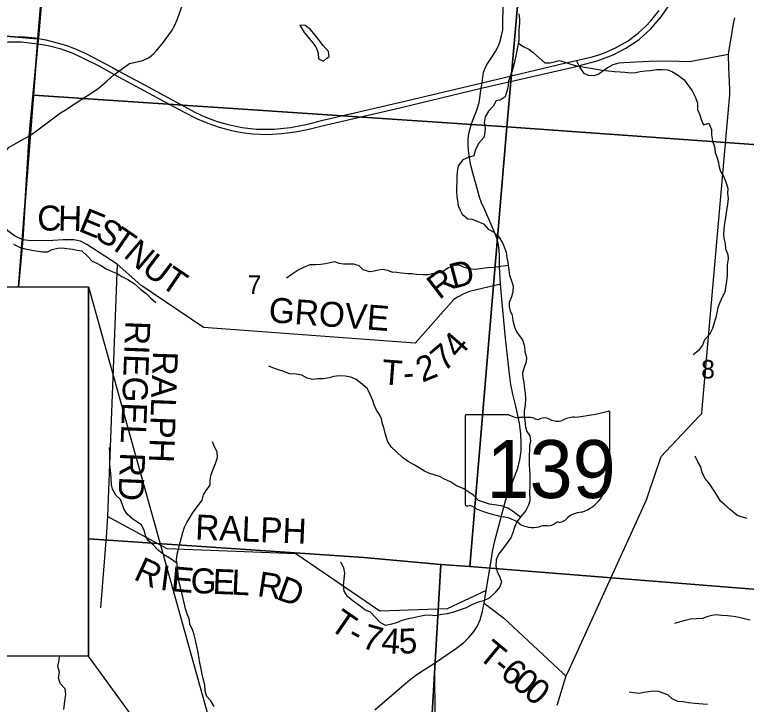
# Model space of a CAD drawing. Extents: x 0 to 34, y 0 to 22.
# Drawn here: x 26.174 to 27.839, y 17.514 to 19.082 of the extents above; entities that cross this region are included whole.
import ezdxf

# ---------------------------------------------------------------- set-up
doc = ezdxf.new("R2010")
doc.units = 0
for name, color, linetype in [('GM_X_Corporation', 7, 'Continuous'), ('GM_X_County_Road', 7, 'Continuous'), ('GM_X_Minor_Lake', 7, 'Continuous'), ('GM_X_Minor_River', 7, 'Continuous'), ('GM_X_Section_Text', 7, 'Continuous'), ('GM_X_State_Location', 7, 'Continuous'), ('GM_X_State_Route', 7, 'Continuous'), ('GM_X_State_Shield', 7, 'Continuous'), ('GM_X_Township_Road', 7, 'Continuous'), ('GM_X_Township_Road_Text', 7, 'Continuous'), ('SH_Data', 7, 'Continuous')]:
    doc.layers.add(name, color=color, linetype=linetype)

msp = doc.modelspace()

# ---------------------------------------------------------------- linework, layer by layer
at = {"layer": 'GM_X_Corporation'}
for points in [[(26.1825, 18.4635), (26.1926, 18.5708), (26.207, 18.8068), (26.2271, 19.0168), (26.2277, 19.0233), (26.2281, 19.0286), (26.3029, 19.931), (25.7174, 19.9778), (25.482, 19.99), (25.2916, 20.0037), (25.117, 20.0172), (24.3889, 20.0736), (24.2296, 20.084), (23.8215, 20.1257), (23.5167, 20.1476), (23.5167, 14.1), (25.8273, 14.1), (25.8671, 14.5774), (25.9626, 15.7291)], [(26.3029, 19.931), (26.2281, 19.0286), (26.2277, 19.0233), (26.2271, 19.0168), (26.207, 18.8068), (26.1926, 18.5708), (26.1825, 18.4635)], [(25.1756, 18.4635), (25.2286, 19.1118), (26.2267, 19.0272), (26.2169, 18.8995), (26.1832, 18.4635)], [(26.1832, 18.4635), (26.2169, 18.8995), (27.2938, 18.8276), (27.2101, 17.8272), (27.1442, 17.8319), (26.9688, 17.8482), (26.3421, 17.8905)], [(26.3421, 17.8905), (26.9688, 17.8482), (27.1442, 17.8319), (27.1132, 17.3107), (27.1145, 16.8163), (26.06, 16.9257), (26.0658, 16.9791), (26.1183, 17.6235)]]:
    msp.add_lwpolyline(points, dxfattribs=at)
for points in [[(26.302, 19.9328), (26.2267, 19.0272), (25.2286, 19.1118), (25.2979, 20.0049)], [(27.3834, 19.8411), (27.2938, 18.8276), (26.2169, 18.8995), (26.2267, 19.0272), (26.302, 19.9328)], [(27.4311, 19.8373), (28.3876, 19.7694), (28.2889, 18.7562), (27.2938, 18.8276), (27.3834, 19.8411)], [(27.2938, 18.8276), (28.2889, 18.7562), (28.2146, 17.7472), (27.2101, 17.8272)], [(27.1442, 17.8319), (27.2101, 17.8272), (28.2146, 17.7472), (28.2741, 17.7417), (28.199, 16.7653), (27.1145, 16.8163), (27.1132, 17.3107)]]:
    msp.add_lwpolyline(points, close=True, dxfattribs=at)
at = {"layer": 'GM_X_County_Road'}
for points in [[(26.4975, 19.0018), (26.5104, 19.017), (26.5312, 19.0447), (26.5381, 19.0566), (26.5437, 19.0706), (26.5623, 19.1231)], [(26.2872, 18.8644), (26.3142, 18.882), (26.3636, 18.9139), (26.3846, 18.9317), (26.4009, 18.9463), (26.403, 18.9479), (26.4085, 18.9518), (26.4115, 18.954), (26.4249, 18.964), (26.4352, 18.9715), (26.4659, 18.9784), (26.4803, 18.9847), (26.491, 18.9942), (26.4975, 19.0018)], [(26.1967, 18.8005), (26.2072, 18.8063), (26.2241, 18.818), (26.2788, 18.8589), (26.2872, 18.8644)], [(25.5296, 18.4635), (25.6325, 18.5008), (25.6385, 18.503), (25.6487, 18.5126), (25.7159, 18.5755), (25.7363, 18.5751), (25.9101, 18.5708), (25.9139, 18.5707), (25.9301, 18.5741), (26.0384, 18.5952), (26.0505, 18.6033), (26.0725, 18.6261), (26.1085, 18.6647), (26.1162, 18.6788), (26.1224, 18.6983), (26.1347, 18.7397), (26.1421, 18.755), (26.1524, 18.7703), (26.1618, 18.7812), (26.1967, 18.8005)]]:
    msp.add_lwpolyline(points, dxfattribs=at)
at = {"layer": 'GM_X_Minor_Lake'}
for points in [[(26.8231, 19.0581), (26.8325, 19.0418), (26.8529, 19.0182), (26.8601, 19.008), (26.8646, 18.9951), (26.8657, 18.9822), (26.8767, 18.9769), (26.8842, 18.9831)], [(26.8842, 18.9831), (26.8896, 18.9875), (26.8881, 18.9989), (26.876, 19.0118), (26.8662, 19.0247), (26.8571, 19.0368), (26.8469, 19.0482), (26.8352, 19.0577), (26.8231, 19.0581)]]:
    msp.add_lwpolyline(points, dxfattribs=at)
at = {"layer": 'GM_X_Minor_River'}
for points in [[(27.3211, 19.0842), (27.3232, 19.0721), (27.3228, 19.0626), (27.3216, 19.0489), (27.3214, 19.0232), (27.3194, 19.0122), (27.3171, 19), (27.3147, 18.9883), (27.312, 18.9781), (27.31, 18.9679), (27.3065, 18.9542), (27.3023, 18.9444), (27.2981, 18.9308), (27.2969, 18.9213), (27.2945, 18.9103), (27.2899, 18.8956), (27.2792, 18.8877), (27.2698, 18.8862), (27.2632, 18.8745), (27.2526, 18.8628), (27.2445, 18.8496), (27.2426, 18.8367), (27.2447, 18.8242), (27.2443, 18.8143), (27.2419, 18.8026), (27.2301, 18.7898), (27.2228, 18.7758), (27.2186, 18.7614), (27.2057, 18.7573), (27.1939, 18.7521), (27.1829, 18.7389), (27.1809, 18.7252), (27.1804, 18.7139), (27.1803, 18.701), (27.1795, 18.6911), (27.1794, 18.6797), (27.1805, 18.6691), (27.1816, 18.6592), (27.1834, 18.6475), (27.1875, 18.638), (27.1923, 18.6284), (27.2055, 18.6177)], [(27.3204, 19.0175), (27.3315, 19.0102), (27.344, 19.0037), (27.3541, 18.996), (27.3677, 18.9838), (27.3805, 18.9731), (27.3918, 18.9726), (27.4024, 18.9748), (27.413, 18.9782), (27.424, 18.9754), (27.4372, 18.9704), (27.4497, 18.9665), (27.4625, 18.9642), (27.475, 18.9618), (27.4852, 18.9606), (27.4984, 18.9586), (27.5109, 18.9559), (27.5253, 18.9543), (27.5389, 18.9531), (27.5517, 18.9522), (27.5627, 18.9514), (27.5767, 18.9501), (27.5865, 18.9505), (27.5972, 18.953), (27.6104, 18.9545), (27.621, 18.9555), (27.6346, 18.9577), (27.6475, 18.9576), (27.66, 18.9568), (27.6706, 18.9525), (27.6845, 18.9441), (27.6977, 18.9338), (27.7074, 18.9208), (27.716, 18.9094), (27.7231, 18.8938), (27.7276, 18.8812), (27.7282, 18.8664), (27.7331, 18.8547), (27.736, 18.844), (27.7413, 18.8318), (27.7534, 18.8356), (27.7597, 18.8215), (27.76, 18.809), (27.7618, 18.7957), (27.7663, 18.7828), (27.7677, 18.7687), (27.7722, 18.7588), (27.7751, 18.7482), (27.7769, 18.7364), (27.7803, 18.7258), (27.7881, 18.7136), (27.7941, 18.698), (27.7966, 18.687), (27.7962, 18.6756), (27.7973, 18.6646), (27.7964, 18.6513), (27.794, 18.6373), (27.7925, 18.6275), (27.7905, 18.6161), (27.7889, 18.6032), (27.7881, 18.593), (27.7869, 18.5835), (27.7879, 18.574), (27.7905, 18.5619), (27.7919, 18.5497), (27.7968, 18.5372), (27.7978, 18.5269), (27.7951, 18.5133), (27.7954, 18.5038), (27.7957, 18.4898), (27.7937, 18.4761), (27.7913, 18.4617), (27.7897, 18.4515), (27.7844, 18.4413), (27.779, 18.4281), (27.7744, 18.4163), (27.7716, 18.4042), (27.7693, 18.394), (27.765, 18.3792), (27.7616, 18.3683), (27.7554, 18.3554), (27.7436, 18.3426), (27.739, 18.3305), (27.7291, 18.318), (27.718, 18.3086)], [(27.2055, 18.6177), (27.2153, 18.6173), (27.2278, 18.6119), (27.2406, 18.6065), (27.2519, 18.5947), (27.2647, 18.5878), (27.276, 18.5771), (27.2842, 18.5637), (27.2879, 18.5542), (27.2924, 18.5424), (27.2942, 18.5295), (27.296, 18.5193), (27.2978, 18.5068), (27.3004, 18.49), (27.3048, 18.4771), (27.3085, 18.465), (27.3077, 18.4517), (27.3046, 18.4407), (27.2992, 18.4279), (27.2991, 18.418), (27.3013, 18.4085), (27.3058, 18.399), (27.3076, 18.3865), (27.3113, 18.3724), (27.3154, 18.3625), (27.3218, 18.353), (27.3293, 18.3431), (27.3345, 18.3286), (27.3351, 18.3165), (27.3384, 18.3024), (27.338, 18.293), (27.3337, 18.2797), (27.3299, 18.2672), (27.3302, 18.257), (27.3328, 18.2456), (27.3345, 18.2308), (27.336, 18.2213), (27.3367, 18.2095), (27.3358, 18.1944), (27.3338, 18.1811), (27.3338, 18.1709), (27.3348, 18.1591), (27.3362, 18.1443), (27.3396, 18.1348), (27.3463, 18.1245), (27.3481, 18.1127), (27.3454, 18.1029), (27.3453, 18.0911), (27.3449, 18.0817), (27.3448, 18.0722), (27.3451, 18.0585), (27.3454, 18.0483), (27.3465, 18.0358), (27.3463, 18.0096), (27.3458, 17.9986), (27.3461, 17.9771)], [(26.1713, 18.5605), (26.1864, 18.5532), (26.1981, 18.5501), (26.2132, 18.5466), (26.2378, 18.5427), (26.2491, 18.543), (26.2594, 18.5486), (26.2727, 18.5515), (26.2833, 18.5518), (26.2931, 18.5506), (26.3063, 18.549), (26.3165, 18.5471), (26.3271, 18.5451), (26.3403, 18.5321), (26.3508, 18.5218), (26.361, 18.5176), (26.3715, 18.511), (26.3825, 18.5045), (26.396, 18.498), (26.407, 18.4934), (26.4179, 18.4872), (26.4315, 18.4799), (26.4462, 18.4707), (26.4612, 18.4577), (26.4736, 18.4482), (26.483, 18.4386), (26.4955, 18.4275)], [(27.2971, 18.5117), (27.2751, 18.5092), (27.2642, 18.5077), (27.2501, 18.5067), (27.2342, 18.5045), (27.2225, 18.5031), (27.2081, 18.5047), (27.1976, 18.507), (27.1859, 18.5124), (27.1734, 18.5121), (27.1601, 18.5058), (27.1475, 18.4979), (27.1354, 18.4946), (27.1248, 18.4931), (27.1153, 18.4909), (27.1036, 18.491), (27.0885, 18.4911), (27.0783, 18.4931), (27.0684, 18.4927), (27.0537, 18.4944), (27.0438, 18.4959), (27.0333, 18.4964), (27.0223, 18.5006), (27.0117, 18.5026), (27.0019, 18.5011), (26.992, 18.4993), (26.9822, 18.4979), (26.9674, 18.5018), (26.9577, 18.5109), (26.9456, 18.5148), (26.9335, 18.5149), (26.9225, 18.5153), (26.9127, 18.5165), (26.9029, 18.52), (26.8911, 18.5182), (26.8813, 18.5156), (26.871, 18.5145), (26.8585, 18.5135), (26.8457, 18.5132), (26.8316, 18.5076), (26.8195, 18.5016), (26.8058, 18.4922), (26.7929, 18.4832)], [(27.2299, 17.9773), (27.2182, 17.9896), (27.2058, 17.9976), (27.196, 18.0038), (27.1794, 18.0111), (27.1662, 18.0199), (27.1523, 18.0264), (27.141, 18.0318), (27.1308, 18.0349), (27.1168, 18.04), (27.1066, 18.0446), (27.0946, 18.0519), (27.0817, 18.0591), (27.0693, 18.0664), (27.0565, 18.0756), (27.0437, 18.0875), (27.0313, 18.0989), (27.0231, 18.1107), (27.0201, 18.121), (27.0171, 18.1309), (27.0149, 18.1404), (27.0112, 18.1522), (27.009, 18.1636), (27.0042, 18.1731), (26.9974, 18.1826), (26.9918, 18.1951), (26.9893, 18.205), (26.9833, 18.2187), (26.977, 18.2313), (26.9649, 18.2424), (26.951, 18.2527), (26.9389, 18.2577), (26.9265, 18.2604), (26.9128, 18.2609), (26.9007, 18.2595), (26.8901, 18.2565), (26.8772, 18.2543), (26.8636, 18.254), (26.8515, 18.253), (26.8394, 18.2561), (26.8273, 18.2622), (26.8145, 18.2646), (26.7993, 18.2658), (26.7869, 18.2712), (26.7771, 18.274), (26.765, 18.2778), (26.7522, 18.2828)], [(26.4147, 17.9797), (26.4042, 17.9896), (26.397, 18.0036), (26.3948, 18.0143), (26.3934, 18.0283), (26.3926, 18.0389), (26.3904, 18.0594), (26.3909, 18.0727), (26.3909, 18.0859), (26.3898, 18.0984)], [(26.6007, 17.9787), (26.6041, 17.9903), (26.6102, 18.0001), (26.6186, 18.0126), (26.6187, 18.022), (26.6207, 18.0345), (26.6261, 18.0485), (26.6311, 18.0618), (26.6353, 18.0754), (26.6347, 18.0883), (26.6283, 18.1009), (26.6242, 18.1108)], [(27.7801, 17.9762), (27.7711, 17.9912), (27.764, 18.0015), (27.7557, 18.0144), (27.7449, 18.0285), (27.7385, 18.0411), (27.7352, 18.054), (27.7285, 18.0658), (27.7225, 18.078)], [(26.5432, 17.8354), (26.5258, 17.847), (26.513, 17.8546), (26.5009, 17.8649), (26.4904, 17.8763), (26.4783, 17.8858), (26.4723, 17.8957), (26.469, 17.9097), (26.4626, 17.9219), (26.452, 17.9288), (26.4422, 17.9356), (26.4309, 17.9455), (26.4234, 17.9569), (26.4147, 17.9797)], [(26.6065, 17.5586), (26.6028, 17.5722), (26.6005, 17.5825), (26.5987, 17.5942), (26.5957, 17.6083), (26.5931, 17.6231), (26.5909, 17.636), (26.5875, 17.6496), (26.5853, 17.6602), (26.5827, 17.6724), (26.579, 17.6845), (26.573, 17.6955), (26.5719, 17.7062), (26.5677, 17.7179), (26.5632, 17.7312), (26.5595, 17.7452), (26.5569, 17.7574), (26.5543, 17.7676), (26.5521, 17.7771), (26.5495, 17.7881), (26.5472, 17.7991), (26.5461, 17.8094), (26.5454, 17.8188), (26.5436, 17.8321), (26.5425, 17.8427), (26.544, 17.8556), (26.5471, 17.867), (26.5506, 17.8817), (26.554, 17.8931), (26.5571, 17.9045), (26.5609, 17.9173), (26.5659, 17.9276), (26.5723, 17.9374), (26.5784, 17.9491), (26.6007, 17.9787)], [(27.3461, 17.9771), (27.3434, 17.9667), (27.3369, 17.9549), (27.3267, 17.9421), (27.3164, 17.9289), (27.3111, 17.9167), (27.3084, 17.9065), (27.3034, 17.8929), (27.2951, 17.8816), (27.2867, 17.8698), (27.2753, 17.8555), (27.27, 17.8426), (27.2691, 17.8293), (27.2721, 17.8157), (27.2774, 17.8058), (27.2815, 17.7929), (27.278, 17.7812), (27.2666, 17.7676), (27.2537, 17.7555), (27.2409, 17.7498), (27.2284, 17.7461), (27.214, 17.7405), (27.2018, 17.7337), (27.1821, 17.7269), (27.1723, 17.7239), (27.1579, 17.7198), (27.1458, 17.7184), (27.1314, 17.7154), (27.1174, 17.717), (27.1064, 17.7159), (27.0951, 17.7136), (27.0814, 17.711), (27.0693, 17.7088), (27.0553, 17.7047), (27.0432, 17.6994), (27.0315, 17.6964), (27.0186, 17.6931), (27.0061, 17.6999), (26.9952, 17.7114), (26.9839, 17.7235), (26.9711, 17.7293), (26.9575, 17.7396), (26.9443, 17.7487), (26.9318, 17.7594), (26.9239, 17.7712), (26.9221, 17.784), (26.9236, 17.7988), (26.9256, 17.8125), (26.923, 17.8246), (26.9162, 17.8371)], [(27.3248, 17.9397), (27.3093, 17.952), (27.2961, 17.9604), (27.281, 17.9658), (27.2544, 17.9694), (27.2299, 17.9773)], [(27.8408, 17.9363), (27.8272, 17.9402), (27.817, 17.944), (27.8026, 17.9566), (27.7902, 17.9676), (27.7801, 17.9762)], [(27.8475, 17.7054), (27.835, 17.7085), (27.8229, 17.7112), (27.8097, 17.7135), (27.7961, 17.7151), (27.7828, 17.7163), (27.77, 17.7175), (27.7598, 17.7164), (27.7492, 17.7134), (27.7389, 17.7093), (27.7249, 17.7082), (27.7117, 17.7075), (27.6996, 17.7049), (27.6886, 17.7015), (27.6753, 17.6978)], [(26.2862, 17.5025), (26.2874, 17.5147), (26.2894, 17.5272), (26.2905, 17.5366), (26.2894, 17.5495), (26.2774, 17.5617), (26.274, 17.5742), (26.2763, 17.5875), (26.2722, 17.6004), (26.2757, 17.6148), (26.276, 17.6235)], [(26.6279, 17.5092), (26.6207, 17.5217), (26.6117, 17.5316), (26.6076, 17.5442), (26.6065, 17.5586)], [(27.7503, 17.514), (27.7401, 17.5144), (27.722, 17.5156), (27.7076, 17.5172), (27.6951, 17.5199), (27.683, 17.5203), (27.6705, 17.5264), (27.6604, 17.536), (27.6494, 17.5398), (27.6392, 17.5429), (27.626, 17.5437), (27.6161, 17.5422), (27.6055, 17.5411), (27.5957, 17.5389), (27.5821, 17.5404), (27.5722, 17.542)]]:
    msp.add_lwpolyline(points, dxfattribs=at)
at = {"layer": 'GM_X_State_Route'}
msp.add_line((27.2359, 18.9148), (27.4588, 18.9662), dxfattribs=at)
for points in [[(27.4588, 18.9662), (27.4595, 18.9664), (27.4998, 18.9775), (27.5357, 18.991), (27.5651, 19.0059), (27.595, 19.0259), (27.6217, 19.05), (27.6448, 19.0777), (27.6634, 19.1041), (27.6789, 19.1351), (27.6893, 19.1642), (27.696, 19.1907), (27.6996, 19.2171), (27.7018, 19.2443), (27.7026, 19.2826), (27.7041, 19.3538), (27.7065, 19.4779), (27.7095, 19.6149), (27.7111, 19.7195), (27.7114, 19.7325)], [(26.9933, 17.5012), (27.0652, 17.5627), (27.0839, 17.5779), (27.0987, 17.5882), (27.1295, 17.6076), (27.1794, 17.6421), (27.1952, 17.6541), (27.2079, 17.666), (27.2173, 17.6774), (27.2265, 17.6908), (27.2334, 17.7064), (27.2385, 17.7263), (27.2421, 17.7439), (27.2467, 17.7732), (27.258, 17.8401), (27.2615, 17.8613), (27.2667, 17.8856), (27.2916, 17.9802), (27.319, 18.0513), (27.3238, 18.0702), (27.3266, 18.0896), (27.3267, 18.1094), (27.3261, 18.1283), (27.3231, 18.1534), (27.3143, 18.1922), (27.3077, 18.2194), (27.3034, 18.2411), (27.2991, 18.2716), (27.2912, 18.3468), (27.2837, 18.4272), (27.2796, 18.4694), (27.2774, 18.5088), (27.2774, 18.533), (27.2764, 18.5478), (27.275, 18.5591), (27.2717, 18.5716), (27.2672, 18.5843), (27.2437, 18.6382), (27.2363, 18.6546), (27.232, 18.6674), (27.2123, 18.7395), (27.2092, 18.7564), (27.2066, 18.7735), (27.2059, 18.7861), (27.2062, 18.7988), (27.2077, 18.8118), (27.2132, 18.8318), (27.2192, 18.8481), (27.226, 18.8655), (27.2312, 18.8828), (27.2359, 18.9148), (27.2376, 18.9276), (27.2406, 18.9517), (27.2478, 18.9673), (27.257, 18.9808), (27.2679, 18.9986), (27.274, 19.0102), (27.2779, 19.0199), (27.2812, 19.0308), (27.2846, 19.0478), (27.2873, 19.2517)], [(26.4115, 18.954), (26.4609, 18.9276), (26.5854, 18.8602), (26.6109, 18.8487), (26.6347, 18.8395), (26.66, 18.8323), (26.6915, 18.8254), (26.724, 18.8222), (26.7648, 18.8222), (26.8015, 18.8257), (26.8412, 18.8334), (26.8752, 18.8421), (27.0523, 18.8834), (27.2376, 18.9276), (27.4286, 18.9724), (27.4524, 18.9779), (27.4718, 18.9825), (27.4881, 18.9867), (27.5059, 18.9918), (27.5217, 18.9979), (27.5431, 19.0075), (27.5703, 19.023), (27.5938, 19.0406), (27.6106, 19.0558), (27.6212, 19.0673), (27.6408, 19.0914)], [(26.168, 19.033), (26.1973, 19.0318), (26.221, 19.0293), (26.2283, 19.0281), (26.2447, 19.0252), (26.2676, 19.0193), (26.2906, 19.0126), (26.3144, 19.0037), (26.3375, 18.9936), (26.3969, 18.9618), (26.4115, 18.954)], [(25.3496, 18.6702), (25.4138, 18.7006), (25.5277, 18.7538), (25.7087, 18.8396), (25.8629, 18.913), (25.981, 18.9686), (26.0152, 18.985), (26.0417, 18.9962), (26.0701, 19.0054), (26.1024, 19.014), (26.1315, 19.0186), (26.1601, 19.0207), (26.1899, 19.0202), (26.2273, 19.0163), (26.2503, 19.012), (26.2766, 19.0051), (26.3063, 18.9944), (26.3317, 18.9829), (26.3654, 18.9656), (26.4009, 18.9463)], [(26.4009, 18.9463), (26.5259, 18.8785), (26.5595, 18.8605), (26.5897, 18.8452), (26.6136, 18.8353), (26.6391, 18.8265), (26.6673, 18.8187), (26.6911, 18.8143), (26.7158, 18.8113), (26.7502, 18.8098), (26.7821, 18.8117), (26.8127, 18.8158), (26.8406, 18.8214), (26.8735, 18.8293), (27.0507, 18.8705), (27.2359, 18.9148)]]:
    msp.add_lwpolyline(points, dxfattribs=at)
at = {"layer": 'GM_X_State_Shield'}
for p, q in [((27.1991, 18.1691), (27.1991, 17.969)), ((27.2989, 18.1726), (27.2023, 18.1726)), ((27.5287, 18.0729), (27.5287, 18.1775)), ((27.5286, 18.0729), (27.5287, 18.0729))]:
    msp.add_line(p, q, dxfattribs=at)
for centre, major_axis, start_param, end_param in [((27.2029, 18.1696), (0.00382, 0), 1.712693, 3.28349), ((27.3218, 18.1958), (0.037, 0), 4.042523, 4.731795), ((27.3341, 18.0602), (0.133, 0), 1.404758, 1.657858), ((27.3643, 18.1706), (0.0107, 0), 3.836095, 5.185415), ((27.38, 18.1475), (0.0222, 0), 0.950623, 2.079405), ((27.4559, 18.1115), (0.0703, 0), 1.699011, 2.107814), ((27.4113, 18.4454), (0.3495, 0), 4.814394, 5.042369), ((27.525, 18.178), (0.00367, 0), 6.141152, 7.989035), ((27.4087, 18.1792), (0.0267, 0), 4.081561, 5.145723), ((27.5278, 18.0652), (0.00568, 0), 1.883978, 3.671073), ((27.5248, 18.0725), (0.00393, 0), 5.05454, 6.418171), ((27.4917, 18.0519), (0.0341, 0), 5.934695, 6.695948), ((27.5418, 18.0291), (0.0248, 0), 2.387724, 3.262537), ((27.4309, 18.0157), (0.0874, 0), 5.101752, 6.440018), ((27.2029, 17.9686), (0.00385, 0), 3.00124, 4.508301), ((27.2035, 17.9891), (0.0294, 0), 4.665946, 4.897461), ((27.2095, 17.9575), (0.0106, 0), 0.519207, 1.627899), ((27.3433, 18.1373), (0.2524, 0), 4.195997, 4.488961), ((27.4677, 17.9128), (0.0479, 0), 1.647645, 2.488434), ((27.2681, 17.8791), (0.079, 0), 0.823519, 1.323587), ((27.4071, 17.9496), (0.0282, 0), 4.937069, 5.64225), ((27.3535, 17.9565), (0.0501, 0), 4.026481, 4.996735), ((27.3824, 17.8873), (0.0412, 0), 1.495662, 1.94098), ((27.3861, 17.9415), (0.0267, 0), 4.691044, 5.507374), ((27.4103, 17.9221), (0.00752, 0), 1.147584, 2.315152)]:
    msp.add_ellipse(centre, major_axis=major_axis, ratio=0.8, start_param=start_param, end_param=end_param, dxfattribs=at)
at = {"layer": 'GM_X_Township_Road'}
msp.add_line((26.3814, 17.8855), (26.3697, 17.7338), dxfattribs=at)
for points in [[(27.7985, 18.9915), (27.8002, 19.002), (27.8108, 19.0649), (27.8125, 19.0754)], [(27.4082, 17.5124), (27.4262, 17.5693), (27.4292, 17.5788), (27.4334, 17.5879), (27.6115, 17.9788), (27.618, 17.9976), (27.6439, 18.0732), (27.6454, 18.0776), (27.6559, 18.0887), (27.7312, 18.1687), (27.7377, 18.1756), (27.7386, 18.1861), (27.801, 18.8925), (27.8015, 18.8996), (27.8011, 18.9124), (27.7994, 18.9623), (27.7985, 18.9915), (27.71, 18.9749), (27.6618, 18.9766), (27.6177, 18.9758), (27.5745, 18.9737), (27.5603, 18.9727)], [(27.5603, 18.9727), (27.5491, 18.9719), (27.5351, 18.9683), (27.5233, 18.9613), (27.5031, 18.947), (27.4917, 18.9429), (27.48, 18.9441), (27.4703, 18.9487), (27.4636, 18.9574), (27.4588, 18.9662), (27.4524, 18.9779)], [(26.2609, 18.5685), (26.2519, 18.568), (26.2052, 18.5687), (26.1928, 18.5702), (26.174, 18.5797), (26.1588, 18.5907), (26.136, 18.6227), (26.1085, 18.6647)], [(27.2796, 18.4694), (27.2087, 18.4525), (27.1946, 18.4471), (27.1816, 18.4398), (27.1737, 18.4344), (27.0856, 18.3351), (26.6036, 18.3711), (26.4611, 18.4673), (26.4072, 18.5147), (26.3387, 18.5599), (26.3241, 18.567), (26.3088, 18.57), (26.2847, 18.57), (26.2609, 18.5685)], [(26.4072, 18.5147), (26.3856, 17.9412), (26.382, 17.8942), (26.3814, 17.8855)], [(27.2467, 17.7732), (27.1579, 17.7309), (27.0052, 17.7259), (26.8136, 17.8566), (26.521, 17.868), (26.3856, 17.9412)], [(27.2421, 17.7439), (27.2868, 17.7109), (27.4217, 17.5851), (27.4292, 17.5788)], [(27.1295, 17.6076), (27.1302, 17.4692), (27.1094, 17.3183), (27.1089, 17.0285), (27.1135, 16.8092), (27.107, 16.5939), (27.1034, 16.3274)]]:
    msp.add_lwpolyline(points, dxfattribs=at)
at = {"layer": 'SH_Data'}
for points in [[(24.656, 18.4635), (26.3421, 18.4635), (26.3421, 17.6235), (24.656, 17.6235)], [(26.3421, 18.4635), (26.7223, 17.1016), (26.3421, 17.6235)]]:
    msp.add_lwpolyline(points, close=True, dxfattribs=at)

# ---------------------------------------------------------------- texts
at = {"layer": 'GM_X_Section_Text'}
for s, p in [('7', (26.7042, 18.4473)), ('8', (27.7362, 18.2551))]:
    msp.add_text(s, height=0.0419, rotation=0, dxfattribs=at).set_placement(p)
at = {"layer": 'GM_X_State_Location'}
for s in ['s', 'r']:
    msp.add_text(s, height=0.000189, dxfattribs=at).set_placement((27.3602, 18.0558))
msp.add_text('139', height=0.000189, rotation=0, dxfattribs=at).set_placement((27.2933, 18.042))
at = {"layer": 'GM_X_State_Shield'}
msp.add_text('139', height=0.13184, dxfattribs=at).set_placement((27.2476, 17.9831))
at = {"layer": 'GM_X_Township_Road_Text'}
for s, height, rotation, p in [('C', 0.0568, 1.1398, (26.2261, 18.5908)), ('H', 0.0568, 358.4662, (26.2721, 18.5917)), ('E', 0.0568, 337.5516, (26.3167, 18.5915)), ('S', 0.0568, 327.3036, (26.3536, 18.5765)), ('T', 0.0568, 325.6835, (26.3855, 18.556)), ('N', 0.0568, 319.5564, (26.4194, 18.533)), ('U', 0.0568, 322.9198, (26.4602, 18.4983)), ('D', 0.0568, 14.6839, (27.1718, 18.4586)), ('T', 0.0568, 325.8906, (26.5028, 18.4663)), ('R', 0.0568, 37.5412, (27.1402, 18.4328)), ('GROVE', 0.05682, 355.7495, (26.7508, 18.3832)), ('RIEGEL RD', 0.05682, 267.7514, (26.4263, 18.387)), ('4', 0.0568, 49.0848, (27.1841, 18.2978)), ('7', 0.0568, 40.1844, (27.1505, 18.2685)), ('RALPH', 0.05682, 267.9025, (26.489, 18.3177)), ('T', 0.0568, 355.6822, (27.0078, 18.242)), ('2', 0.0568, 22.3835, (27.1017, 18.2452)), ('-', 0.0568, 4.5826, (27.0598, 18.2389)), ('RALPH', 0.05682, 357.6931, (26.5842, 17.8891)), ('R', 0.0568, 335.2976, (26.4424, 17.7994)), ('I', 0.0568, 352.8112, (26.503, 17.7748)), ('E', 0.0568, 354.9951, (26.5285, 17.7716)), ('G', 0.0568, 357.4761, (26.5735, 17.7677)), ('E', 0.0568, 357.7111, (26.6237, 17.7655)), ('L', 0.0568, 357.2733, (26.666, 17.7638)), ('R', 0.0568, 351.0651, (26.7243, 17.7606)), ('D', 0.0568, 339.8115, (26.7676, 17.7541)), ('T', 0.0568, 325.3764, (26.8874, 17.6872)), ('7', 0.0568, 343.8115, (26.9608, 17.6435)), ('4', 0.0568, 356.1016, (27.0074, 17.6314)), ('5', 0.0568, 2.2466, (27.049, 17.6289)), ('-', 0.0568, 331.5214, (26.928, 17.6596)), ('T', 0.0568, 320.4159, (27.2256, 17.6212)), ('-', 0.0568, 320.4156, (27.2583, 17.5942)), ('6', 0.0568, 320.4145, (27.2761, 17.5795)), ('0', 0.0568, 320.4107, (27.3028, 17.5573)), ('0', 0.0568, 320.3786, (27.3296, 17.5352))]:
    msp.add_text(s, height=height, rotation=rotation, dxfattribs=at).set_placement(p)

doc.saveas('drawing.dxf')
